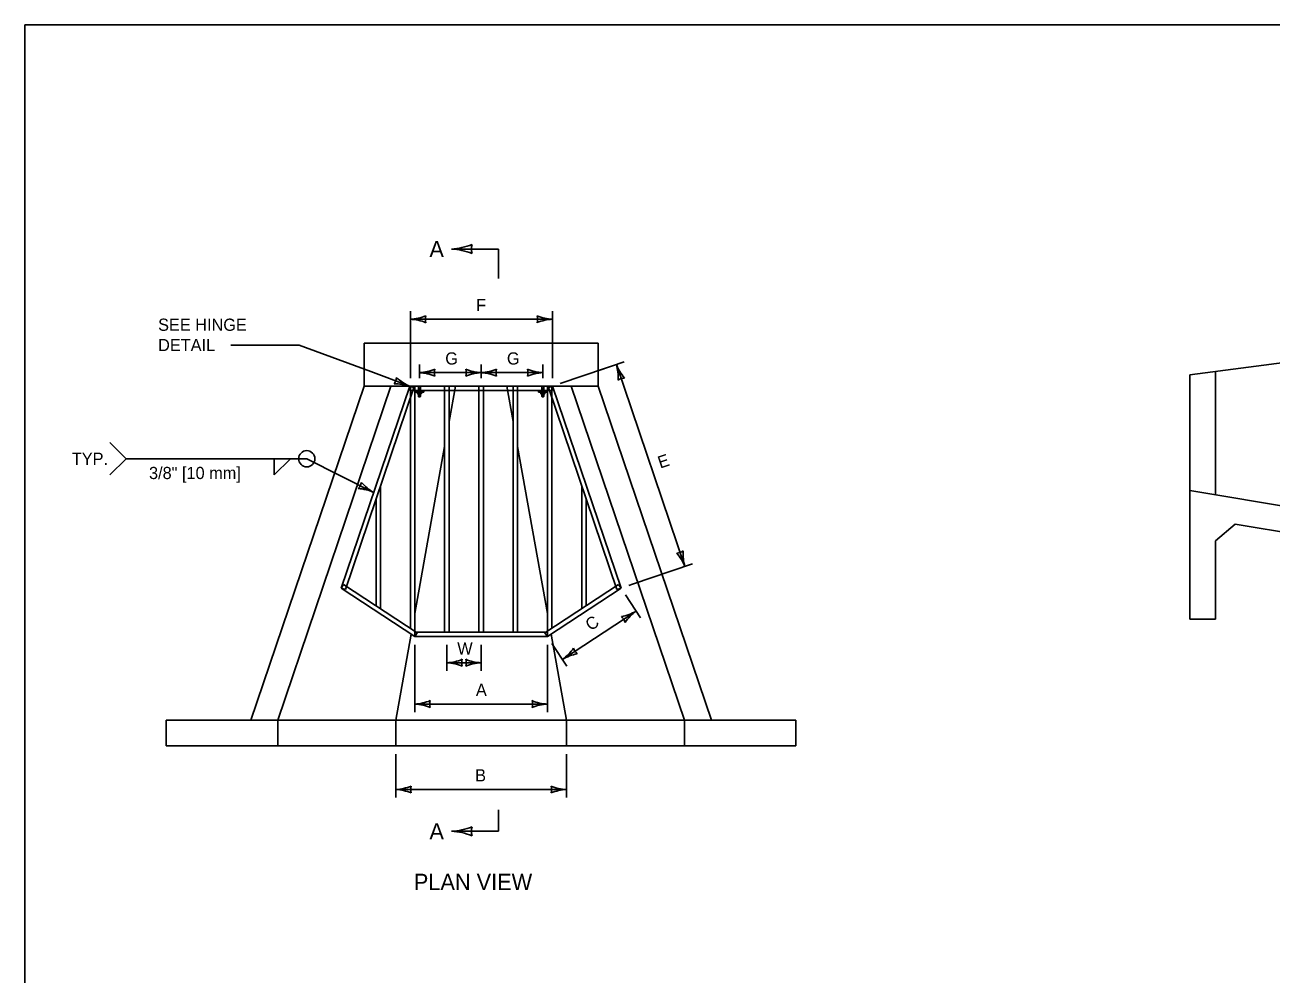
# Model space of a CAD drawing. Extents: x 49991.4 to 50021, y 49987.6 to 50011.4.
# Drawn here: x 49999.38 to 50005.52, y 49994.33 to 49999 of the extents above; entities that cross this region are included whole.
import ezdxf

# ---------------------------------------------------------------- set-up
doc = ezdxf.new("R2010")
doc.units = 0
for name, color, linetype in [('Level 1', 7, 'Continuous'), ('Level 2', 7, 'Continuous'), ('Level 3', 7, 'Continuous'), ('Level 4', 7, 'Continuous'), ('Level 6', 7, 'Continuous')]:
    doc.layers.add(name, color=color, linetype=linetype)

msp = doc.modelspace()

# ---------------------------------------------------------------- linework, layer by layer
at = {"layer": 'Level 1'}
for p, q in [((50005.12, 49997.2756), (50006.8919, 49997.5076)), ((50001.0534, 49997.4317), (50002.2066, 49997.4317)), ((50001.0534, 49997.2207), (50001.0534, 49997.4317)), ((50002.2066, 49997.2207), (50002.2066, 49997.4317)), ((50005.12, 49996.0732), (50005.12, 49997.2756)), ((50001.0534, 49997.2207), (50000.4952, 49995.5754)), ((50001.186, 49997.2207), (50000.6289, 49995.5754)), ((50001.2782, 49997.2207), (50000.9407, 49996.226)), ((50001.2991, 49997.2137), (50000.9616, 49996.2189)), ((50001.0534, 49997.2207), (50002.2066, 49997.2207)), ((50001.2991, 49997.2137), (50001.2782, 49997.2207)), ((50001.2782, 49997.2207), (50001.2782, 49997.1986)), ((50001.2782, 49997.1986), (50001.9818, 49997.1986)), ((50001.2814, 49997.2207), (50001.2814, 49996.0286)), ((50001.3036, 49997.2207), (50001.3036, 49996.014)), ((50001.3052, 49997.1986), (50001.3052, 49997.1907)), ((50001.3473, 49997.1986), (50001.3052, 49997.1986)), ((50001.3052, 49997.1907), (50001.3473, 49997.1907)), ((50001.3355, 49997.1907), (50001.317, 49997.1907)), ((50001.317, 49997.1822), (50001.317, 49997.1907)), ((50001.3326, 49997.1814), (50001.32, 49997.1814)), ((50001.321, 49997.1986), (50001.321, 49997.2207)), ((50001.321, 49997.2105), (50001.3315, 49997.2105)), ((50001.321, 49997.2085), (50001.3315, 49997.2085)), ((50001.321, 49997.2065), (50001.3315, 49997.2065)), ((50001.321, 49997.2045), (50001.3315, 49997.2045)), ((50001.321, 49997.2026), (50001.3315, 49997.2026)), ((50001.321, 49997.2006), (50001.3315, 49997.2006)), ((50001.321, 49997.1814), (50001.321, 49997.1693)), ((50001.321, 49997.1792), (50001.3315, 49997.1792)), ((50001.321, 49997.1772), (50001.3315, 49997.1772)), ((50001.321, 49997.1753), (50001.3315, 49997.1753)), ((50001.321, 49997.1733), (50001.3315, 49997.1733)), ((50001.321, 49997.1713), (50001.3315, 49997.1713)), ((50001.3223, 49997.168), (50001.321, 49997.1693)), ((50001.321, 49997.1693), (50001.3315, 49997.1693)), ((50001.3223, 49997.2095), (50001.3302, 49997.2095)), ((50001.3223, 49997.2075), (50001.3302, 49997.2075)), ((50001.3223, 49997.2055), (50001.3302, 49997.2055)), ((50001.3223, 49997.2035), (50001.3302, 49997.2035)), ((50001.3223, 49997.2016), (50001.3302, 49997.2016)), ((50001.3223, 49997.1996), (50001.3302, 49997.1996)), ((50001.3223, 49997.1822), (50001.3223, 49997.1907)), ((50001.3223, 49997.1802), (50001.3302, 49997.1802)), ((50001.3223, 49997.1782), (50001.3302, 49997.1782)), ((50001.3223, 49997.1762), (50001.3302, 49997.1762)), ((50001.3223, 49997.1743), (50001.3302, 49997.1743)), ((50001.3223, 49997.1723), (50001.3302, 49997.1723)), ((50001.3223, 49997.1703), (50001.3302, 49997.1703)), ((50001.3302, 49997.1822), (50001.3302, 49997.1907)), ((50001.3302, 49997.168), (50001.3315, 49997.1693)), ((50001.3315, 49997.1986), (50001.3315, 49997.2207)), ((50001.3315, 49997.1814), (50001.3315, 49997.1693)), ((50001.3355, 49997.1822), (50001.3355, 49997.1907)), ((50001.3473, 49997.1986), (50001.3473, 49997.1907)), ((50001.4502, 49997.2207), (50001.4502, 49996.0098)), ((50001.4723, 49997.2207), (50001.4723, 49996.0098)), ((50001.5034, 49997.2207), (50001.4723, 49997.0465)), ((50001.6189, 49997.2207), (50001.6189, 49996.0098)), ((50001.6411, 49997.2207), (50001.6411, 49996.0098)), ((50001.7566, 49997.2207), (50001.7877, 49997.0465)), ((50001.7877, 49997.2207), (50001.7877, 49996.0098)), ((50001.8098, 49997.2207), (50001.8098, 49996.0098)), ((50001.9127, 49997.1986), (50001.9127, 49997.1907)), ((50001.9548, 49997.1907), (50001.9127, 49997.1907)), ((50001.9245, 49997.1822), (50001.9245, 49997.1907)), ((50001.9276, 49997.1814), (50001.9399, 49997.1814)), ((50001.9285, 49997.1986), (50001.9285, 49997.2207)), ((50001.939, 49997.2105), (50001.9285, 49997.2105)), ((50001.939, 49997.2085), (50001.9285, 49997.2085)), ((50001.939, 49997.2065), (50001.9285, 49997.2065)), ((50001.939, 49997.2045), (50001.9285, 49997.2045)), ((50001.939, 49997.2026), (50001.9285, 49997.2026)), ((50001.939, 49997.2006), (50001.9285, 49997.2006)), ((50001.9285, 49997.1814), (50001.9285, 49997.1693)), ((50001.939, 49997.1792), (50001.9285, 49997.1792)), ((50001.939, 49997.1772), (50001.9285, 49997.1772)), ((50001.939, 49997.1753), (50001.9285, 49997.1753)), ((50001.939, 49997.1733), (50001.9285, 49997.1733)), ((50001.939, 49997.1713), (50001.9285, 49997.1713)), ((50001.9298, 49997.168), (50001.9285, 49997.1693)), ((50001.939, 49997.1693), (50001.9285, 49997.1693)), ((50001.9377, 49997.2095), (50001.9298, 49997.2095)), ((50001.9377, 49997.2075), (50001.9298, 49997.2075)), ((50001.9377, 49997.2055), (50001.9298, 49997.2055)), ((50001.9377, 49997.2035), (50001.9298, 49997.2035)), ((50001.9377, 49997.2016), (50001.9298, 49997.2016)), ((50001.9377, 49997.1996), (50001.9298, 49997.1996)), ((50001.9298, 49997.1822), (50001.9298, 49997.1907)), ((50001.9377, 49997.1802), (50001.9298, 49997.1802)), ((50001.9377, 49997.1782), (50001.9298, 49997.1782)), ((50001.9377, 49997.1762), (50001.9298, 49997.1762)), ((50001.9377, 49997.1743), (50001.9298, 49997.1743)), ((50001.9377, 49997.1723), (50001.9298, 49997.1723)), ((50001.9377, 49997.1703), (50001.9298, 49997.1703)), ((50001.9377, 49997.1822), (50001.9377, 49997.1907)), ((50001.9377, 49997.168), (50001.939, 49997.1693)), ((50001.939, 49997.1986), (50001.939, 49997.2207)), ((50001.939, 49997.1814), (50001.939, 49997.1693)), ((50001.943, 49997.1822), (50001.943, 49997.1907)), ((50001.9548, 49997.1986), (50001.9548, 49997.1907)), ((50001.9564, 49997.2207), (50001.9564, 49996.014)), ((50001.9609, 49997.2137), (50001.9818, 49997.2207)), ((50001.9609, 49997.2137), (50002.2984, 49996.2189)), ((50001.9786, 49997.2207), (50001.9786, 49996.0285)), ((50001.9818, 49997.2207), (50002.3193, 49996.226)), ((50001.9818, 49997.2207), (50001.9818, 49997.1986)), ((50002.073, 49997.2207), (50002.6312, 49995.5754)), ((50002.2066, 49997.2207), (50002.7648, 49995.5754)), ((50001.3302, 49997.168), (50001.3223, 49997.168)), ((50001.9298, 49997.168), (50001.9377, 49997.168)), ((50001.4502, 49996.9227), (50001.3036, 49996.1016)), ((50001.8098, 49996.9228), (50001.9564, 49996.1018)), ((50001.1348, 49996.7294), (50001.1348, 49996.1249)), ((50002.1252, 49996.7294), (50002.1252, 49996.1249)), ((50006.8919, 49996.4107), (50005.12, 49996.7061)), ((50001.1127, 49996.6641), (50001.1127, 49996.1395)), ((50002.1473, 49996.6642), (50002.1473, 49996.1394)), ((50005.2465, 49996.4588), (50005.3431, 49996.5406)), ((50006.6385, 49996.3247), (50005.3431, 49996.5406)), ((50005.2465, 49996.4588), (50005.2465, 49996.0732)), ((50000.9407, 49996.226), (50000.9528, 49996.2445)), ((50000.9407, 49996.226), (50001.3035, 49995.9876)), ((50000.9616, 49996.2189), (50000.9407, 49996.226)), ((50000.9528, 49996.2445), (50001.3157, 49996.0061)), ((50001.9444, 49996.0061), (50002.3072, 49996.2445)), ((50001.9565, 49995.9876), (50002.3193, 49996.226)), ((50002.2984, 49996.2189), (50002.3193, 49996.226)), ((50002.3193, 49996.226), (50002.3072, 49996.2445)), ((50005.12, 49996.0732), (50005.2465, 49996.0732)), ((50001.9565, 49996.0098), (50001.3035, 49996.0098)), ((50001.3035, 49996.0098), (50001.3035, 49995.9876)), ((50001.3157, 49996.0061), (50001.3035, 49995.9876)), ((50001.9565, 49995.9876), (50001.9444, 49996.0061)), ((50001.9565, 49996.0098), (50001.9565, 49995.9876)), ((50001.2853, 49995.9995), (50001.2096, 49995.5754)), ((50001.9565, 49995.9876), (50001.3035, 49995.9876)), ((50001.9747, 49995.9995), (50002.0504, 49995.5754)), ((50000.0796, 49995.4489), (50000.0796, 49995.5754)), ((50000.0796, 49995.5754), (50003.1804, 49995.5754)), ((50000.6289, 49995.5754), (50000.6289, 49995.4489)), ((50001.2096, 49995.5754), (50001.2096, 49995.4489)), ((50002.0504, 49995.5754), (50002.0504, 49995.4489)), ((50002.6312, 49995.5754), (50002.6312, 49995.4487)), ((50003.1804, 49995.4489), (50003.1804, 49995.5754)), ((50000.0796, 49995.4489), (50003.1804, 49995.4489))]:
    msp.add_line(p, q, dxfattribs=at)
msp.add_lwpolyline([(49999.3835, 49998.9992), (50016.7501, 49998.9992), (50016.7501, 49987.7988), (49999.3835, 49987.7988)], close=True, dxfattribs=at)
for centre, radius, start, end in [((50001.3196, 49997.186), 0.00461, 235.43748, 305.54263), ((50001.3263, 49997.1975), 0.0158, 255.34669, 284.2639), ((50001.3328, 49997.186), 0.00461, 235.22217, 305.34074), ((50001.9271, 49997.186), 0.00461, 235.22217, 305.33712), ((50001.9338, 49997.1975), 0.0158, 255.42131, 284.33841), ((50001.9403, 49997.186), 0.00461, 235.22217, 305.3511)]:
    msp.add_arc(centre, radius, start, end, dxfattribs=at)
at = {"layer": 'Level 3'}
for p, q in [((50001.2814, 49997.2607), (50001.2814, 49997.59)), ((50001.2814, 49997.55), (50001.9818, 49997.55)), ((50001.9818, 49997.2607), (50001.9818, 49997.59)), ((50000.3972, 49997.4231), (50000.7345, 49997.4231)), ((50000.7345, 49997.4231), (50001.0861, 49997.2922)), ((50001.0861, 49997.2922), (50001.2782, 49997.2207)), ((50001.3262, 49997.2607), (50001.3262, 49997.3271)), ((50001.63, 49997.2607), (50001.63, 49997.3271)), ((50001.9337, 49997.2607), (50001.9337, 49997.3271)), ((50002.0197, 49997.2336), (50002.2423, 49997.3091)), ((50002.2045, 49997.2964), (50002.3337, 49997.3402)), ((50002.2958, 49997.3273), (50002.6333, 49996.3325)), ((50001.63, 49997.2871), (50001.3262, 49997.2871)), ((50001.9337, 49997.2871), (50001.63, 49997.2871)), ((49999.8013, 49996.9432), (49999.8813, 49996.8632)), ((49999.8013, 49996.7832), (49999.8813, 49996.8632)), ((49999.8813, 49996.8632), (50000.7713, 49996.8632)), ((50000.6113, 49996.8632), (50000.6113, 49996.7832)), ((50000.6113, 49996.7832), (50000.6913, 49996.8632)), ((50001.1007, 49996.6976), (50000.7713, 49996.8632)), ((50002.3752, 49996.245), (50002.6712, 49996.3454)), ((50002.3413, 49996.1926), (50002.4153, 49996.08)), ((50002.3572, 49996.2389), (50002.3752, 49996.245)), ((50002.0306, 49995.875), (50002.3933, 49996.1134)), ((50001.3035, 49995.9476), (50001.3035, 49995.6154)), ((50001.4612, 49995.8188), (50001.4612, 49995.9476)), ((50001.63, 49995.9476), (50001.63, 49995.8188)), ((50001.9565, 49995.9476), (50001.9565, 49995.6154)), ((50001.9786, 49995.9543), (50002.0525, 49995.8416)), ((50001.63, 49995.8588), (50001.4612, 49995.8588)), ((50001.9565, 49995.6554), (50001.3035, 49995.6554)), ((50001.2096, 49995.4089), (50001.2096, 49995.1947)), ((50002.0504, 49995.4089), (50002.0504, 49995.1947)), ((50001.2096, 49995.2347), (50002.0504, 49995.2347))]:
    msp.add_line(p, q, dxfattribs=at)
msp.add_circle((50000.7713, 49996.8632), 0.04, dxfattribs=at)
for centre, radius, start, end in [((50001.4687, 49998.2061), 0.3107, 272.82731, 292.07716), ((50001.6549, 49997.8959), 0.073, 162.13882, 197.86118), ((50001.4718, 49997.5997), 0.2964, 67.45601, 87.63952), ((50001.2699, 49997.7827), 0.233, 272.82731, 292.07716), ((50001.2722, 49997.3278), 0.2223, 67.45601, 87.63952), ((50001.4096, 49997.55), 0.0548, 162.13882, 197.86118), ((50001.9909, 49997.7721), 0.2223, 247.45601, 267.63952), ((50001.8536, 49997.55), 0.0548, 342.13882, 17.86118), ((50001.9933, 49997.3173), 0.233, 92.82731, 112.07716), ((50001.3147, 49997.5198), 0.233, 272.82731, 292.07716), ((50001.4544, 49997.2871), 0.0548, 162.13882, 197.86118), ((50001.6391, 49997.5092), 0.2223, 247.45601, 267.63952), ((50001.5018, 49997.2871), 0.0548, 342.13882, 17.86118), ((50001.6185, 49997.5198), 0.233, 272.82731, 292.07716), ((50001.7582, 49997.2871), 0.0548, 162.13882, 197.86118), ((50001.9428, 49997.5092), 0.2223, 247.45601, 267.63952), ((50001.8055, 49997.2871), 0.0548, 342.13882, 17.86118), ((50002.0825, 49997.2646), 0.2223, 356.19624, 16.37975), ((50002.5125, 49997.413), 0.233, 201.56754, 220.81739), ((50001.158, 49997.2654), 0.0548, 321.72033, 357.44269), ((50001.2078, 49996.9986), 0.233, 72.40882, 91.65867), ((50001.3643, 49997.4256), 0.2223, 227.03752, 247.22102), ((50001.317, 49997.0649), 0.2223, 67.45601, 87.63952), ((50001.6415, 49997.0544), 0.233, 92.82731, 112.07716), ((50001.6208, 49997.0649), 0.2223, 67.45601, 87.63952), ((50001.9452, 49997.0544), 0.233, 92.82731, 112.07716), ((50002.337, 49997.2059), 0.0548, 90.87905, 126.60141), ((50000.9861, 49996.7552), 0.0548, 315.44867, 351.17103), ((50001.2087, 49996.8919), 0.2223, 220.76586, 240.94937), ((50001.0064, 49996.4845), 0.233, 66.13716, 85.38701), ((50002.5921, 49996.4539), 0.0548, 270.87905, 306.60141), ((50002.4166, 49996.2469), 0.233, 21.56754, 40.81739), ((50002.8466, 49996.3952), 0.2223, 176.19624, 196.37975), ((50002.279, 49996.3041), 0.2223, 280.76538, 300.94889), ((50002.2862, 49996.043), 0.0548, 15.44819, 51.17055), ((50002.5307, 49995.9252), 0.233, 126.13668, 145.38653), ((50001.8932, 49996.0632), 0.233, 306.13668, 325.38653), ((50002.1449, 49995.6843), 0.2223, 100.76538, 120.94889), ((50002.1377, 49995.9454), 0.0548, 195.44819, 231.17055), ((50001.4497, 49996.0915), 0.233, 272.82731, 292.07716), ((50001.452, 49995.6366), 0.2223, 67.45601, 87.63952), ((50001.5894, 49995.8588), 0.0548, 162.13882, 197.86118), ((50001.6391, 49996.0809), 0.2223, 247.45601, 267.63952), ((50001.5018, 49995.8588), 0.0548, 342.13882, 17.86118), ((50001.6415, 49995.6261), 0.233, 92.82731, 112.07716), ((50001.292, 49995.8881), 0.233, 272.82731, 292.07716), ((50001.2943, 49995.4332), 0.2223, 67.45601, 87.63952), ((50001.4317, 49995.6554), 0.0548, 162.13882, 197.86118), ((50001.9656, 49995.8775), 0.2223, 247.45601, 267.63952), ((50001.8283, 49995.6554), 0.0548, 342.13882, 17.86118), ((50001.968, 49995.4227), 0.233, 92.82731, 112.07716), ((50001.1981, 49995.4674), 0.233, 272.82731, 292.07716), ((50001.2005, 49995.0125), 0.2223, 67.45601, 87.63952), ((50001.3378, 49995.2347), 0.0548, 162.13882, 197.86118), ((50002.0596, 49995.4568), 0.2223, 247.45601, 267.63952), ((50001.9222, 49995.2347), 0.0548, 342.13882, 17.86118), ((50002.0619, 49995.002), 0.233, 92.82731, 112.07716), ((50001.4687, 49995.3392), 0.3107, 272.82731, 292.07716), ((50001.4718, 49994.7328), 0.2964, 67.45601, 87.63952), ((50001.6549, 49995.029), 0.073, 162.13882, 197.86118)]:
    msp.add_arc(centre, radius, start, end, dxfattribs=at)
at = {"layer": 'Level 4'}
for p, q in [((50005.2465, 49996.685), (50005.2465, 49997.2921)), ((50001.321, 49997.1986), (50001.321, 49997.1907)), ((50001.3315, 49997.1986), (50001.3315, 49997.1907)), ((50001.9285, 49997.1986), (50001.9285, 49997.1907)), ((50001.939, 49997.1986), (50001.939, 49997.1907))]:
    msp.add_line(p, q, dxfattribs=at)
at = {"layer": 'Level 6'}
for p, q in [((50001.7151, 49997.8959), (50001.484, 49997.8959)), ((50001.7151, 49997.75), (50001.7151, 49997.8959)), ((50001.7151, 49995.029), (50001.7151, 49995.1347)), ((50001.7151, 49995.029), (50001.484, 49995.029))]:
    msp.add_line(p, q, dxfattribs=at)

# ---------------------------------------------------------------- texts
at = {"layer": 'Level 2'}
for s, height, p in [('A', 0.08, (50001.3753, 49997.8558)), ('F', 0.06, (50001.6054, 49997.59)), ('SEE HINGE ', 0.06, (50000.0393, 49997.4931)), ('DETAIL', 0.06, (50000.0393, 49997.3931)), ('G', 0.06, (50001.4533, 49997.3271)), ('G', 0.06, (50001.757, 49997.3271)), ('TYP.', 0.06, (49999.6144, 49996.8332)), ('3/8" [10 mm]', 0.06, (49999.9946, 49996.7632)), ('W', 0.06, (50001.5124, 49995.8988)), ('A', 0.06, (50001.6042, 49995.6954)), ('B', 0.06, (50001.6005, 49995.2747)), ('A', 0.0799, (50001.3754, 49994.989)), ('PLAN VIEW', 0.08, (50001.2987, 49994.7398))]:
    msp.add_text(s, height=height, dxfattribs=at).set_placement(p)
for s, rotation, p in [('E', 18.7402, (50002.512, 49996.8144)), ('C', 33.30228, (50002.1684, 49996.0134))]:
    msp.add_text(s, height=0.06, rotation=rotation, dxfattribs=at).set_placement(p)

doc.saveas('drawing.dxf')
